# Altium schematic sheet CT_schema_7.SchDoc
size 277 x 170 mm
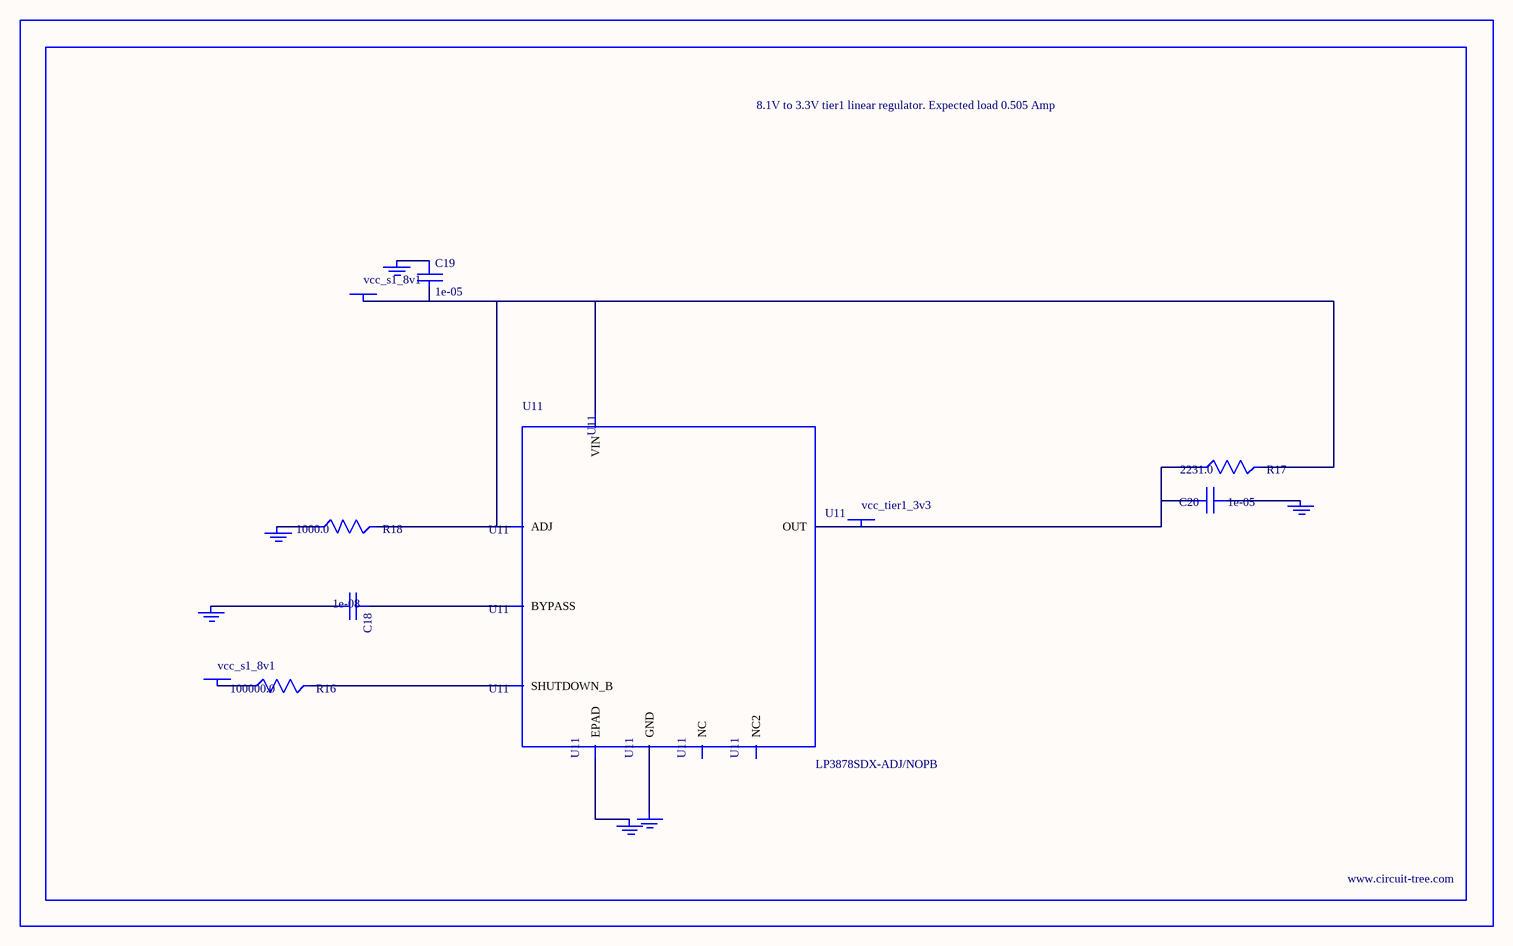
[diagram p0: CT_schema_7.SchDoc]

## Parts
BORDER6  (no value)
C18  1e-08  [C0402]
C19  1e-05  [C1206]
C20  1e-05  [C1210]
GND_INSTANCE_6_0  (no value)
GND_INSTANCE_6_1  (no value)
GND_INSTANCE_6_2  (no value)
GND_INSTANCE_6_3  (no value)
GND_INSTANCE_6_4  (no value)
GND_INSTANCE_6_5  (no value)
POWER_INSTANCE_6_0  vcc_s1_8v1
POWER_INSTANCE_6_1  vcc_s1_8v1
POWER_INSTANCE_6_2  vcc_tier1_3v3
R16  100000.0  [R0603]
R17  2231.0  [R0603]
R18  1000.0  [R0603]
U11  LP3878SDX-ADJ/NOPB  [WSON-8]

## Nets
NetC18_1: C18.1 U11.1(BYPASS)
NetC18_2: C18.2 GND_INSTANCE_6_0.0(GND)
NetC19_1: C19.1 GND_INSTANCE_6_1.0(GND)
NetC19_2: C19.2 POWER_INSTANCE_6_0.0(PWR) R17.2 R18.2 U11.4(VIN) U11.6(ADJ)
NetC20_1: C20.1 GND_INSTANCE_6_2.0(GND)
NetC20_2: C20.2 POWER_INSTANCE_6_2.0(PWR) R17.1 U11.5(OUT)
NetGND_INSTANCE_6_3_0: GND_INSTANCE_6_3.0(GND) R18.1
NetGND_INSTANCE_6_4_0: GND_INSTANCE_6_4.0(GND) U11.PAD(EPAD)
NetGND_INSTANCE_6_5_0: GND_INSTANCE_6_5.0(GND) U11.3(GND)
NetPOWER_INSTANCE_6_1_0: POWER_INSTANCE_6_1.0(PWR) R16.1
NetR16_2: R16.2 U11.8(SHUTDOWN_B)

Not connected (* = marked no-connect by the designer): U11 2(NC) 7(NC2)

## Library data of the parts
BORDER6 = BORDER_PAGE6
C18 = C0402C103K3RAC
C19 = C1206C106K3RACTU
C20 = GRM32DR61E106MA12L
GND_INSTANCE_6_0-GND_INSTANCE_6_5 = GND
POWER_INSTANCE_6_0-POWER_INSTANCE_6_2 = PWR
R16 = RC0603JR-07100KL
R17 = R17
R18 = RC0603JR-071KL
